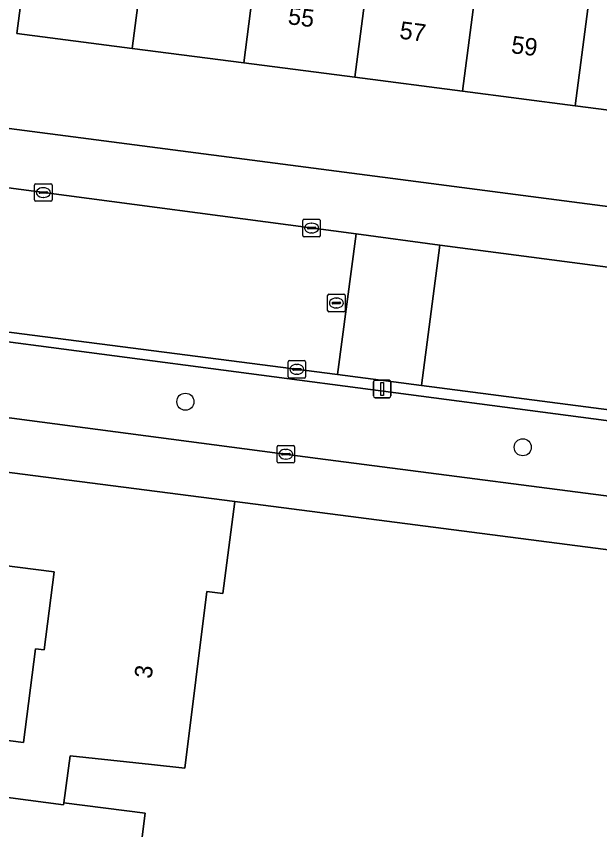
# Model space of a CAD drawing. Extents: x 162184 to 163154, y 385507 to 386516.
# Drawn here: x 162395.31 to 162428.73, y 386100.35 to 386146.91 of the extents above; entities that cross this region are included whole.
import ezdxf

# ---------------------------------------------------------------- set-up
doc = ezdxf.new("R2010")
doc.units = 0
for name, color, linetype in [('IMGEO_Boom', 7, 'Continuous'), ('IMGEO_Erf', 7, 'Continuous'), ('IMGEO_Groenvoorziening', 7, 'Continuous'), ('IMGEO_Kolk', 7, 'Continuous'), ('IMGEO_Lichtmast', 7, 'Continuous'), ('IMGEO_Muur', 7, 'Continuous'), ('IMGEO_Pand', 7, 'Continuous'), ('IMGEO_Pand_nummerreeks', 7, 'Continuous'), ('IMGEO_Rijbaan_lokaal_gesloten', 7, 'Continuous'), ('IMGEO_Rijbaan_lokaal_open', 7, 'Continuous'), ('IMGEO_Rioolput', 7, 'Continuous'), ('IMGEO_Voetpad_open', 7, 'Continuous')]:
    doc.layers.add(name, color=color, linetype=linetype)

msp = doc.modelspace()

# ---------------------------------------------------------------- linework, layer by layer
at = {"layer": 'IMGEO_Boom'}
for centre in [(162404.998, 386124.851), (162424.318, 386122.242)]:
    msp.add_circle(centre, 0.489, dxfattribs=at)
at = {"layer": 'IMGEO_Erf'}
for points in [[(162345.395, 386146.93), (162477.513, 386129.721), (162478.217, 386135.069), (162471.78, 386135.916), (162465.433, 386136.751), (162459.26, 386137.563), (162452.79, 386138.415), (162446.605, 386139.228), (162439.92, 386140.108), (162440.573, 386145.066), (162440.929, 386147.77), (162447.617, 386146.89), (162453.802, 386146.076), (162460.272, 386145.225), (162466.445, 386144.413), (162472.792, 386143.578), (162479.226, 386142.731), (162480.617, 386153.295)], [(162430.108, 386116.262), (162407.83, 386119.134), (162407.151, 386113.873), (162406.228, 386113.986), (162404.967, 386103.874), (162403.05, 386104.082), (162398.406, 386104.586), (162398.034, 386101.902), (162402.695, 386101.305), (162402.02, 386096.032)]]:
    msp.add_lwpolyline(points, dxfattribs=at)
for points in [[(162428.311, 386149.398), (162434.686, 386148.573), (162434.343, 386145.923), (162433.702, 386140.964), (162427.322, 386141.79), (162420.876, 386142.624), (162414.701, 386143.423), (162408.339, 386144.246), (162401.959, 386145.072), (162395.349, 386145.927), (162395.991, 386150.886), (162396.025, 386151.145), (162396.334, 386153.537), (162402.948, 386152.681), (162409.328, 386151.855), (162415.69, 386151.032), (162421.865, 386150.232)], [(162397.487, 386115.107), (162387.42, 386116.401), (162388.099, 386121.683), (162382.521, 386122.36), (162380.067, 386103.971), (162382.951, 386103.601), (162382.971, 386103.758), (162383.379, 386106.936), (162395.728, 386105.35), (162396.417, 386110.706), (162396.913, 386110.643)]]:
    msp.add_lwpolyline(points, close=True, dxfattribs=at)
at = {"layer": 'IMGEO_Groenvoorziening'}
for points in [[(162433.897, 386123.153), (162374.947, 386130.882)], [(162374.32, 386126.635), (162412.591, 386121.605), (162433.217, 386118.933)]]:
    msp.add_lwpolyline(points, dxfattribs=at)
at = {"layer": 'IMGEO_Kolk'}
for p, q in [((162396.363, 386136.395), (162396.363, 386137.247)), ((162396.438, 386137.321), (162397.29, 386137.321)), ((162396.851, 386137.101), (162396.876, 386137.101)), ((162397.364, 386137.247), (162397.364, 386136.395)), ((162396.622, 386136.815), (162396.622, 386136.827)), ((162397.06, 386136.778), (162396.662, 386136.778)), ((162396.665, 386136.864), (162397.063, 386136.864)), ((162396.874, 386136.541), (162396.849, 386136.541)), ((162397.106, 386136.827), (162397.106, 386136.815)), ((162397.29, 386136.321), (162396.438, 386136.321)), ((162411.726, 386134.363), (162411.726, 386135.215)), ((162411.801, 386135.289), (162412.653, 386135.289)), ((162412.214, 386135.069), (162412.239, 386135.069)), ((162412.727, 386135.215), (162412.727, 386134.363)), ((162411.985, 386134.783), (162411.985, 386134.795)), ((162412.423, 386134.746), (162412.025, 386134.746)), ((162412.028, 386134.832), (162412.426, 386134.832)), ((162412.469, 386134.795), (162412.469, 386134.783)), ((162412.653, 386134.289), (162411.801, 386134.289)), ((162412.237, 386134.509), (162412.212, 386134.509)), ((162410.883, 386126.276), (162410.883, 386127.128)), ((162410.958, 386127.202), (162411.81, 386127.202)), ((162411.884, 386127.128), (162411.884, 386126.276)), ((162411.142, 386126.696), (162411.142, 386126.708)), ((162411.185, 386126.745), (162411.583, 386126.745)), ((162411.371, 386126.982), (162411.396, 386126.982)), ((162411.626, 386126.708), (162411.626, 386126.696)), ((162411.81, 386126.202), (162410.958, 386126.202)), ((162411.58, 386126.659), (162411.182, 386126.659)), ((162411.394, 386126.422), (162411.369, 386126.422)), ((162410.253, 386121.419), (162410.253, 386122.271)), ((162410.328, 386122.345), (162411.18, 386122.345)), ((162410.741, 386122.125), (162410.766, 386122.125)), ((162411.254, 386122.271), (162411.254, 386121.419)), ((162410.512, 386121.839), (162410.512, 386121.851)), ((162410.95, 386121.802), (162410.552, 386121.802)), ((162410.555, 386121.888), (162410.953, 386121.888)), ((162410.764, 386121.565), (162410.739, 386121.565)), ((162410.996, 386121.851), (162410.996, 386121.839)), ((162411.18, 386121.345), (162410.328, 386121.345))]:
    msp.add_line(p, q, dxfattribs=at)
for points in [[(162396.363, 386136.395), (162396.363, 386137.247)], [(162396.438, 386137.321), (162397.29, 386137.321)], [(162397.364, 386137.247), (162397.364, 386136.395)], [(162397.29, 386136.321), (162396.438, 386136.321)], [(162411.726, 386134.363), (162411.726, 386135.215)], [(162411.801, 386135.289), (162412.653, 386135.289)], [(162412.727, 386135.215), (162412.727, 386134.363)], [(162412.653, 386134.289), (162411.801, 386134.289)], [(162410.883, 386126.276), (162410.883, 386127.128)], [(162410.958, 386127.202), (162411.81, 386127.202)], [(162411.884, 386127.128), (162411.884, 386126.276)], [(162411.81, 386126.202), (162410.958, 386126.202)], [(162410.253, 386121.419), (162410.253, 386122.271)], [(162410.328, 386122.345), (162411.18, 386122.345)], [(162411.254, 386122.271), (162411.254, 386121.419)], [(162411.18, 386121.345), (162410.328, 386121.345)]]:
    msp.add_lwpolyline(points, dxfattribs=at)
for centre, radius, start, end in [((162396.44, 386137.245), 0.0765, 91.552, 178.448), ((162396.44, 386137.245), 0.0765, 91.552, 178.448), ((162397.288, 386137.245), 0.0765, 1.552, 88.448), ((162397.288, 386137.245), 0.0765, 1.552, 88.448), ((162396.662, 386136.824), 0.0403, 85.8775, 175.7526), ((162396.659, 386136.814), 0.0366, 178.938, 274.7102), ((162397.063, 386136.821), 0.043, 264.8664, 352.4533), ((162397.067, 386136.826), 0.0386, 1.7309, 96.639), ((162396.44, 386136.397), 0.0765, 181.552, 268.448), ((162396.44, 386136.397), 0.0765, 181.552, 268.448), ((162397.288, 386136.397), 0.0765, 271.552, 358.448), ((162397.288, 386136.397), 0.0765, 271.552, 358.448), ((162411.803, 386135.213), 0.0765, 91.552, 178.448), ((162411.803, 386135.213), 0.0765, 91.552, 178.448), ((162412.651, 386135.213), 0.0765, 1.552, 88.448), ((162412.651, 386135.213), 0.0765, 1.552, 88.448), ((162412.025, 386134.792), 0.0403, 85.8775, 175.7526), ((162412.022, 386134.782), 0.0366, 178.938, 274.7102), ((162412.426, 386134.789), 0.043, 264.8664, 352.4533), ((162412.43, 386134.794), 0.0386, 1.7309, 96.639), ((162411.803, 386134.365), 0.0765, 181.552, 268.448), ((162411.803, 386134.365), 0.0765, 181.552, 268.448), ((162412.651, 386134.365), 0.0765, 271.552, 358.448), ((162412.651, 386134.365), 0.0765, 271.552, 358.448), ((162410.96, 386127.126), 0.0765, 91.552, 178.448), ((162410.96, 386127.126), 0.0765, 91.552, 178.448), ((162411.808, 386127.126), 0.0765, 1.552, 88.448), ((162411.808, 386127.126), 0.0765, 1.552, 88.448), ((162411.182, 386126.705), 0.0403, 85.8775, 175.7526), ((162411.179, 386126.695), 0.0366, 178.938, 274.7102), ((162411.583, 386126.702), 0.043, 264.8664, 352.4533), ((162411.587, 386126.707), 0.0386, 1.7309, 96.639), ((162410.96, 386126.278), 0.0765, 181.552, 268.448), ((162410.96, 386126.278), 0.0765, 181.552, 268.448), ((162411.808, 386126.278), 0.0765, 271.552, 358.448), ((162411.808, 386126.278), 0.0765, 271.552, 358.448), ((162410.33, 386122.269), 0.0765, 91.552, 178.448), ((162410.33, 386122.269), 0.0765, 91.552, 178.448), ((162411.178, 386122.269), 0.0765, 1.552, 88.448), ((162411.178, 386122.269), 0.0765, 1.552, 88.448), ((162410.552, 386121.848), 0.0403, 85.8775, 175.7526), ((162410.549, 386121.838), 0.0366, 178.938, 274.7102), ((162410.953, 386121.845), 0.043, 264.8664, 352.4533), ((162410.957, 386121.85), 0.0386, 1.7309, 96.639), ((162410.33, 386121.421), 0.0765, 181.552, 268.448), ((162410.33, 386121.421), 0.0765, 181.552, 268.448), ((162411.178, 386121.421), 0.0765, 271.552, 358.448), ((162411.178, 386121.421), 0.0765, 271.552, 358.448)]:
    msp.add_arc(centre, radius, start, end, dxfattribs=at)
for centre, major_axis, ratio, start_param, end_param in [((162396.85, 386136.821), (-0.387, 0.002), 0.722429, 4.712389, 7.853982), ((162396.875, 386136.821), (-0.39, 0.002), 0.717154, 1.570796, 4.712389), ((162412.213, 386134.789), (-0.387, 0.002), 0.722429, 4.712389, 7.853982), ((162412.238, 386134.789), (-0.39, 0.002), 0.717154, 1.570796, 4.712389), ((162411.37, 386126.702), (-0.387, 0.002), 0.722429, 4.712389, 7.853982), ((162411.395, 386126.702), (-0.39, 0.002), 0.717154, 1.570796, 4.712389), ((162410.74, 386121.845), (-0.387, 0.002), 0.722429, 4.712389, 7.853982), ((162410.765, 386121.845), (-0.39, 0.002), 0.717154, 1.570796, 4.712389)]:
    msp.add_ellipse(centre, major_axis=major_axis, ratio=ratio, start_param=start_param, end_param=end_param, dxfattribs=at)
at = {"layer": 'IMGEO_Lichtmast'}
for p, q in [((162415.77, 386125.179), (162415.77, 386125.979)), ((162415.77, 386125.979), (162415.77, 386125.179)), ((162415.87, 386126.079), (162416.66, 386126.079)), ((162416.66, 386126.079), (162415.87, 386126.079)), ((162416.76, 386125.979), (162416.76, 386125.179)), ((162416.76, 386125.179), (162416.76, 386125.979)), ((162416.66, 386125.079), (162415.87, 386125.079)), ((162415.87, 386125.079), (162416.66, 386125.079))]:
    msp.add_line(p, q, dxfattribs=at)
msp.add_lwpolyline([(162416.19, 386125.954), (162416.34, 386125.954), (162416.34, 386125.204), (162416.19, 386125.204), (162416.19, 386125.954)], dxfattribs=at)
for centre, start, end in [((162415.87, 386125.979), 90, 180), ((162415.87, 386125.979), 90, 180), ((162416.66, 386125.979), 0, 90), ((162416.66, 386125.979), 360, 90), ((162415.87, 386125.179), 180, 270), ((162415.87, 386125.179), 180, 270), ((162416.66, 386125.179), 270, 0), ((162416.66, 386125.179), 270, 0)]:
    msp.add_arc(centre, 0.1, start, end, dxfattribs=at)
at = {"layer": 'IMGEO_Muur'}
msp.add_lwpolyline([(162407.83, 386119.134), (162430.108, 386116.262)], dxfattribs=at)
at = {"layer": 'IMGEO_Pand'}
for points in [[(162402.948, 386152.681), (162396.334, 386153.537), (162396.025, 386151.145), (162395.991, 386150.886), (162395.349, 386145.927), (162401.959, 386145.072)], [(162409.328, 386151.855), (162402.948, 386152.681), (162401.959, 386145.072), (162408.339, 386144.246)], [(162408.339, 386144.246), (162414.701, 386143.423), (162415.69, 386151.032), (162409.328, 386151.855)], [(162414.701, 386143.423), (162420.876, 386142.624), (162421.865, 386150.232), (162415.69, 386151.032)], [(162428.311, 386149.398), (162421.865, 386150.232), (162420.876, 386142.624), (162427.322, 386141.79)], [(162427.322, 386141.79), (162433.702, 386140.964), (162434.343, 386145.923), (162434.686, 386148.573), (162428.311, 386149.398)], [(162388.099, 386121.683), (162387.42, 386116.401), (162397.487, 386115.107), (162396.913, 386110.643), (162396.417, 386110.706), (162395.728, 386105.35), (162383.379, 386106.936), (162382.971, 386103.758), (162398.016, 386101.772), (162398.034, 386101.902), (162398.406, 386104.586), (162403.05, 386104.082), (162404.967, 386103.874), (162406.228, 386113.986), (162407.151, 386113.873), (162407.83, 386119.134)], [(162401.129, 386096.126), (162402.02, 386096.032), (162402.695, 386101.305), (162398.034, 386101.902), (162398.016, 386101.772), (162382.971, 386103.758), (162382.951, 386103.601), (162380.067, 386103.971), (162379.417, 386098.915), (162382.301, 386098.544), (162392.368, 386097.25), (162391.788, 386092.737), (162391.292, 386092.8), (162390.603, 386087.444), (162378.254, 386089.03), (162377.844, 386085.841), (162391.901, 386084.049), (162391.923, 386084.208), (162392.295, 386086.949), (162397.931, 386086.235), (162399.834, 386085.994)]]:
    msp.add_lwpolyline(points, close=True, dxfattribs=at)
at = {"layer": 'IMGEO_Rijbaan_lokaal_gesloten'}
for points in [[(162349.248, 386134.706), (162413.706, 386126.402), (162414.771, 386134.451), (162394.285, 386137.161), (162387.999, 386137.992), (162350.777, 386142.911)], [(162483.155, 386125.393), (162478.798, 386125.983), (162439.406, 386131.193), (162431.953, 386132.179), (162419.58, 386133.815), (162418.517, 386125.775), (162458.948, 386120.525), (162482.119, 386117.517)]]:
    msp.add_lwpolyline(points, dxfattribs=at)
at = {"layer": 'IMGEO_Rijbaan_lokaal_open'}
msp.add_lwpolyline([(162418.517, 386125.775), (162419.58, 386133.815), (162414.771, 386134.451), (162413.706, 386126.402)], close=True, dxfattribs=at)
at = {"layer": 'IMGEO_Rioolput'}
for p, q in [((162413.144, 386130.075), (162413.144, 386130.927)), ((162413.219, 386131.001), (162414.071, 386131.001)), ((162414.145, 386130.927), (162414.145, 386130.075)), ((162413.403, 386130.495), (162413.403, 386130.507)), ((162413.841, 386130.458), (162413.443, 386130.458)), ((162413.446, 386130.544), (162413.844, 386130.544)), ((162413.632, 386130.781), (162413.657, 386130.781)), ((162413.887, 386130.507), (162413.887, 386130.495)), ((162414.071, 386130.001), (162413.219, 386130.001)), ((162413.655, 386130.221), (162413.63, 386130.221))]:
    msp.add_line(p, q, dxfattribs=at)
for points in [[(162413.144, 386130.075), (162413.144, 386130.927)], [(162413.219, 386131.001), (162414.071, 386131.001)], [(162414.145, 386130.927), (162414.145, 386130.075)], [(162414.071, 386130.001), (162413.219, 386130.001)]]:
    msp.add_lwpolyline(points, dxfattribs=at)
for centre, radius, start, end in [((162413.221, 386130.925), 0.0765, 91.552, 178.448), ((162413.221, 386130.925), 0.0765, 91.552, 178.448), ((162414.069, 386130.925), 0.0765, 1.552, 88.448), ((162414.069, 386130.925), 0.0765, 1.552, 88.448), ((162413.443, 386130.504), 0.0403, 85.8775, 175.7526), ((162413.44, 386130.494), 0.0366, 178.938, 274.7102), ((162413.844, 386130.501), 0.043, 264.8664, 352.4533), ((162413.848, 386130.506), 0.0386, 1.7309, 96.639), ((162413.221, 386130.077), 0.0765, 181.552, 268.448), ((162413.221, 386130.077), 0.0765, 181.552, 268.448), ((162414.069, 386130.077), 0.0765, 271.552, 358.448), ((162414.069, 386130.077), 0.0765, 271.552, 358.448)]:
    msp.add_arc(centre, radius, start, end, dxfattribs=at)
for centre, major_axis, ratio, start_param, end_param in [((162413.631, 386130.501), (-0.387, 0.002), 0.722429, 4.712389, 7.853982), ((162413.656, 386130.501), (-0.39, 0.002), 0.717154, 1.570796, 4.712389)]:
    msp.add_ellipse(centre, major_axis=major_axis, ratio=ratio, start_param=start_param, end_param=end_param, dxfattribs=at)
at = {"layer": 'IMGEO_Voetpad_open'}
for points in [[(162503.083, 386125.373), (162498.874, 386126.939), (162479.088, 386129.516), (162477.513, 386129.721), (162345.395, 386146.93), (162342.796, 386147.231), (162310.208, 386151.62), (162307.719, 386151.881), (162300.419, 386152.832), (162280.789, 386155.39), (162279.545, 386155.552), (162276.659, 386155.928), (162272.878, 386156.421), (162272.377, 386156.487), (162267.776, 386157.086), (162265.987, 386157.319), (162263.283, 386157.672), (162261.989, 386154.265)], [(162350.777, 386142.911), (162387.999, 386137.992), (162388.064, 386138.487), (162394.35, 386137.656), (162394.285, 386137.161), (162414.771, 386134.451), (162419.58, 386133.815), (162431.953, 386132.179), (162432.091, 386133.22), (162439.544, 386132.234), (162439.406, 386131.193), (162478.798, 386125.983), (162478.939, 386127.024), (162483.675, 386126.382), (162483.523, 386125.263)], [(162335.977, 386136.365), (162310.353, 386139.77), (162310.282, 386139.248), (162340.574, 386135.313), (162343.99, 386134.88), (162370.427, 386131.472), (162370.591, 386131.46), (162374.85, 386130.906), (162374.947, 386130.882), (162433.897, 386123.153), (162433.998, 386123.151), (162438.832, 386122.519), (162438.968, 386122.49), (162481.668, 386117.141), (162482.448, 386117.039), (162488.462, 386116.238), (162488.565, 386116.214), (162502.033, 386114.344), (162550.987, 386107.982)], [(162482.119, 386117.517), (162458.948, 386120.525), (162418.517, 386125.775), (162413.706, 386126.402), (162349.248, 386134.706)], [(162319.033, 386130.38), (162332.132, 386128.681), (162335.109, 386128.306), (162373.204, 386123.496), (162379.704, 386122.675), (162382.521, 386122.36), (162388.099, 386121.683), (162407.83, 386119.134), (162430.108, 386116.262), (162449.855, 386113.717), (162455.485, 386112.99), (162457.918, 386112.66), (162478.348, 386109.886), (162500, 386107.017), (162527.457, 386103.379), (162530.464, 386102.981), (162535.156, 386102.359), (162549.072, 386100.544)], [(162433.217, 386118.933), (162412.591, 386121.605), (162374.32, 386126.635)]]:
    msp.add_lwpolyline(points, dxfattribs=at)

# ---------------------------------------------------------------- texts
at = {"layer": 'IMGEO_Pand_nummerreeks'}
for s, rotation, p in [('55', 352.6267, (162410.834, 386146.464)), ('57', 352.6267, (162417.226, 386145.637)), ('59', 352.6267, (162423.618, 386144.81)), ('3', 82.8917, (162403.063, 386108.969))]:
    msp.add_text(s, height=1, rotation=rotation, dxfattribs=at).set_placement(p)

doc.saveas('drawing.dxf')
